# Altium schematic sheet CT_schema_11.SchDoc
size 742 x 377 mm
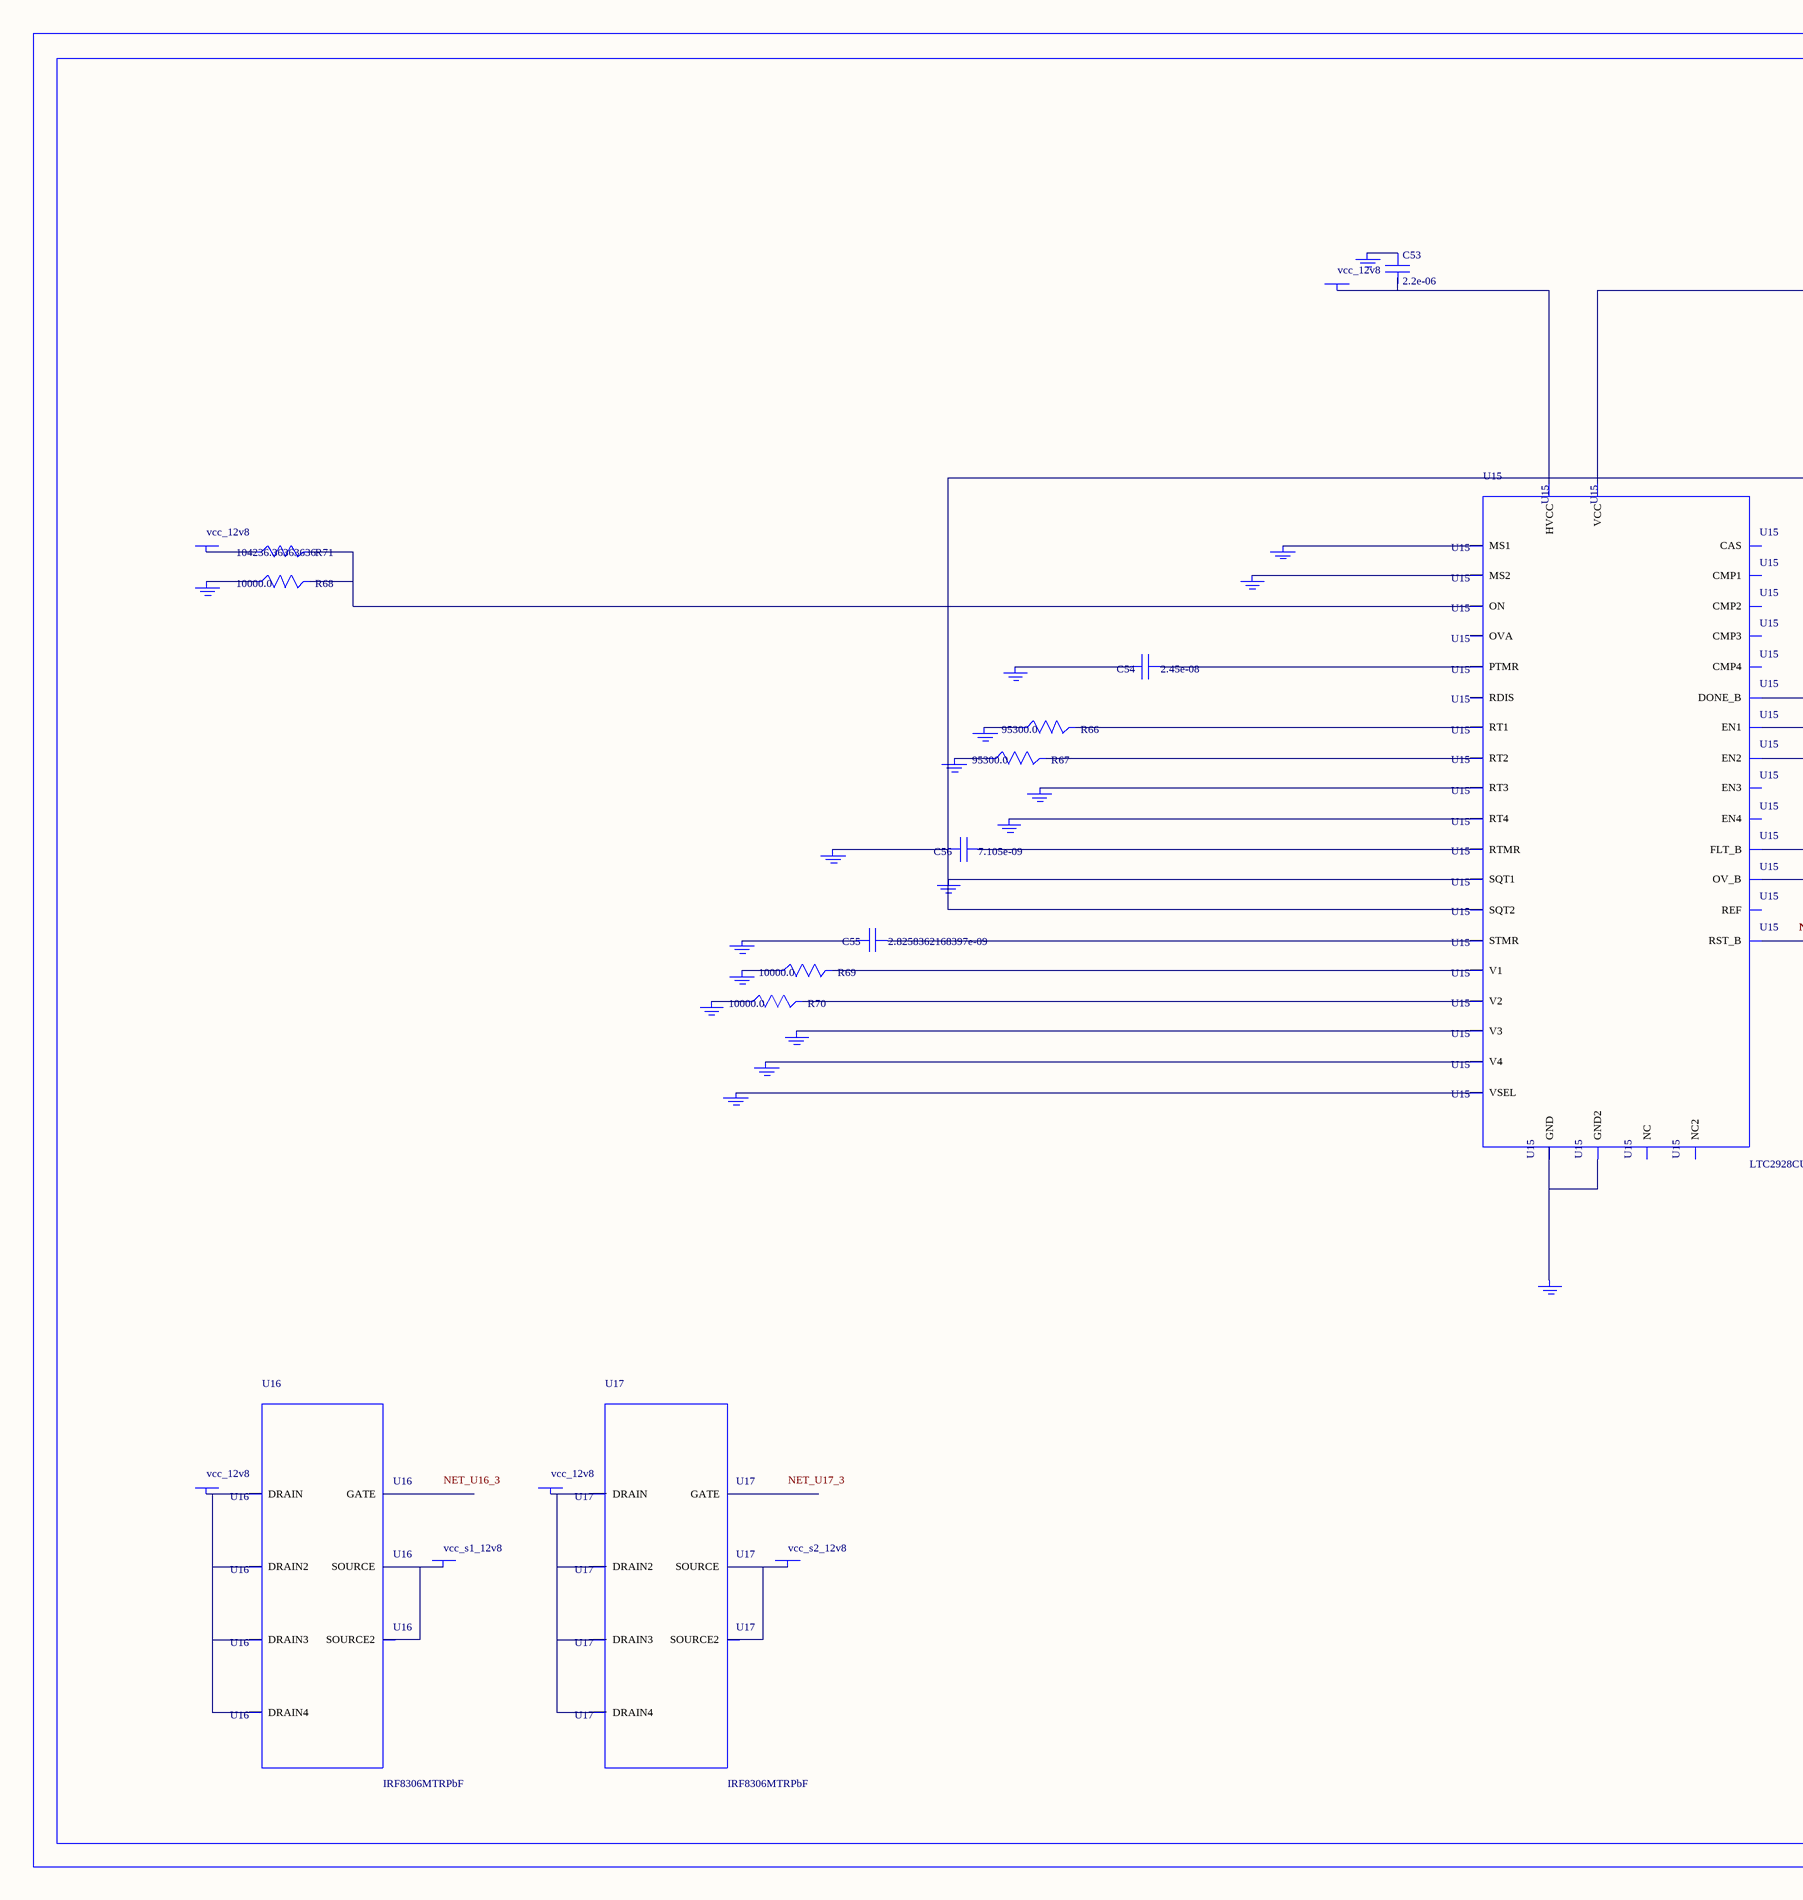
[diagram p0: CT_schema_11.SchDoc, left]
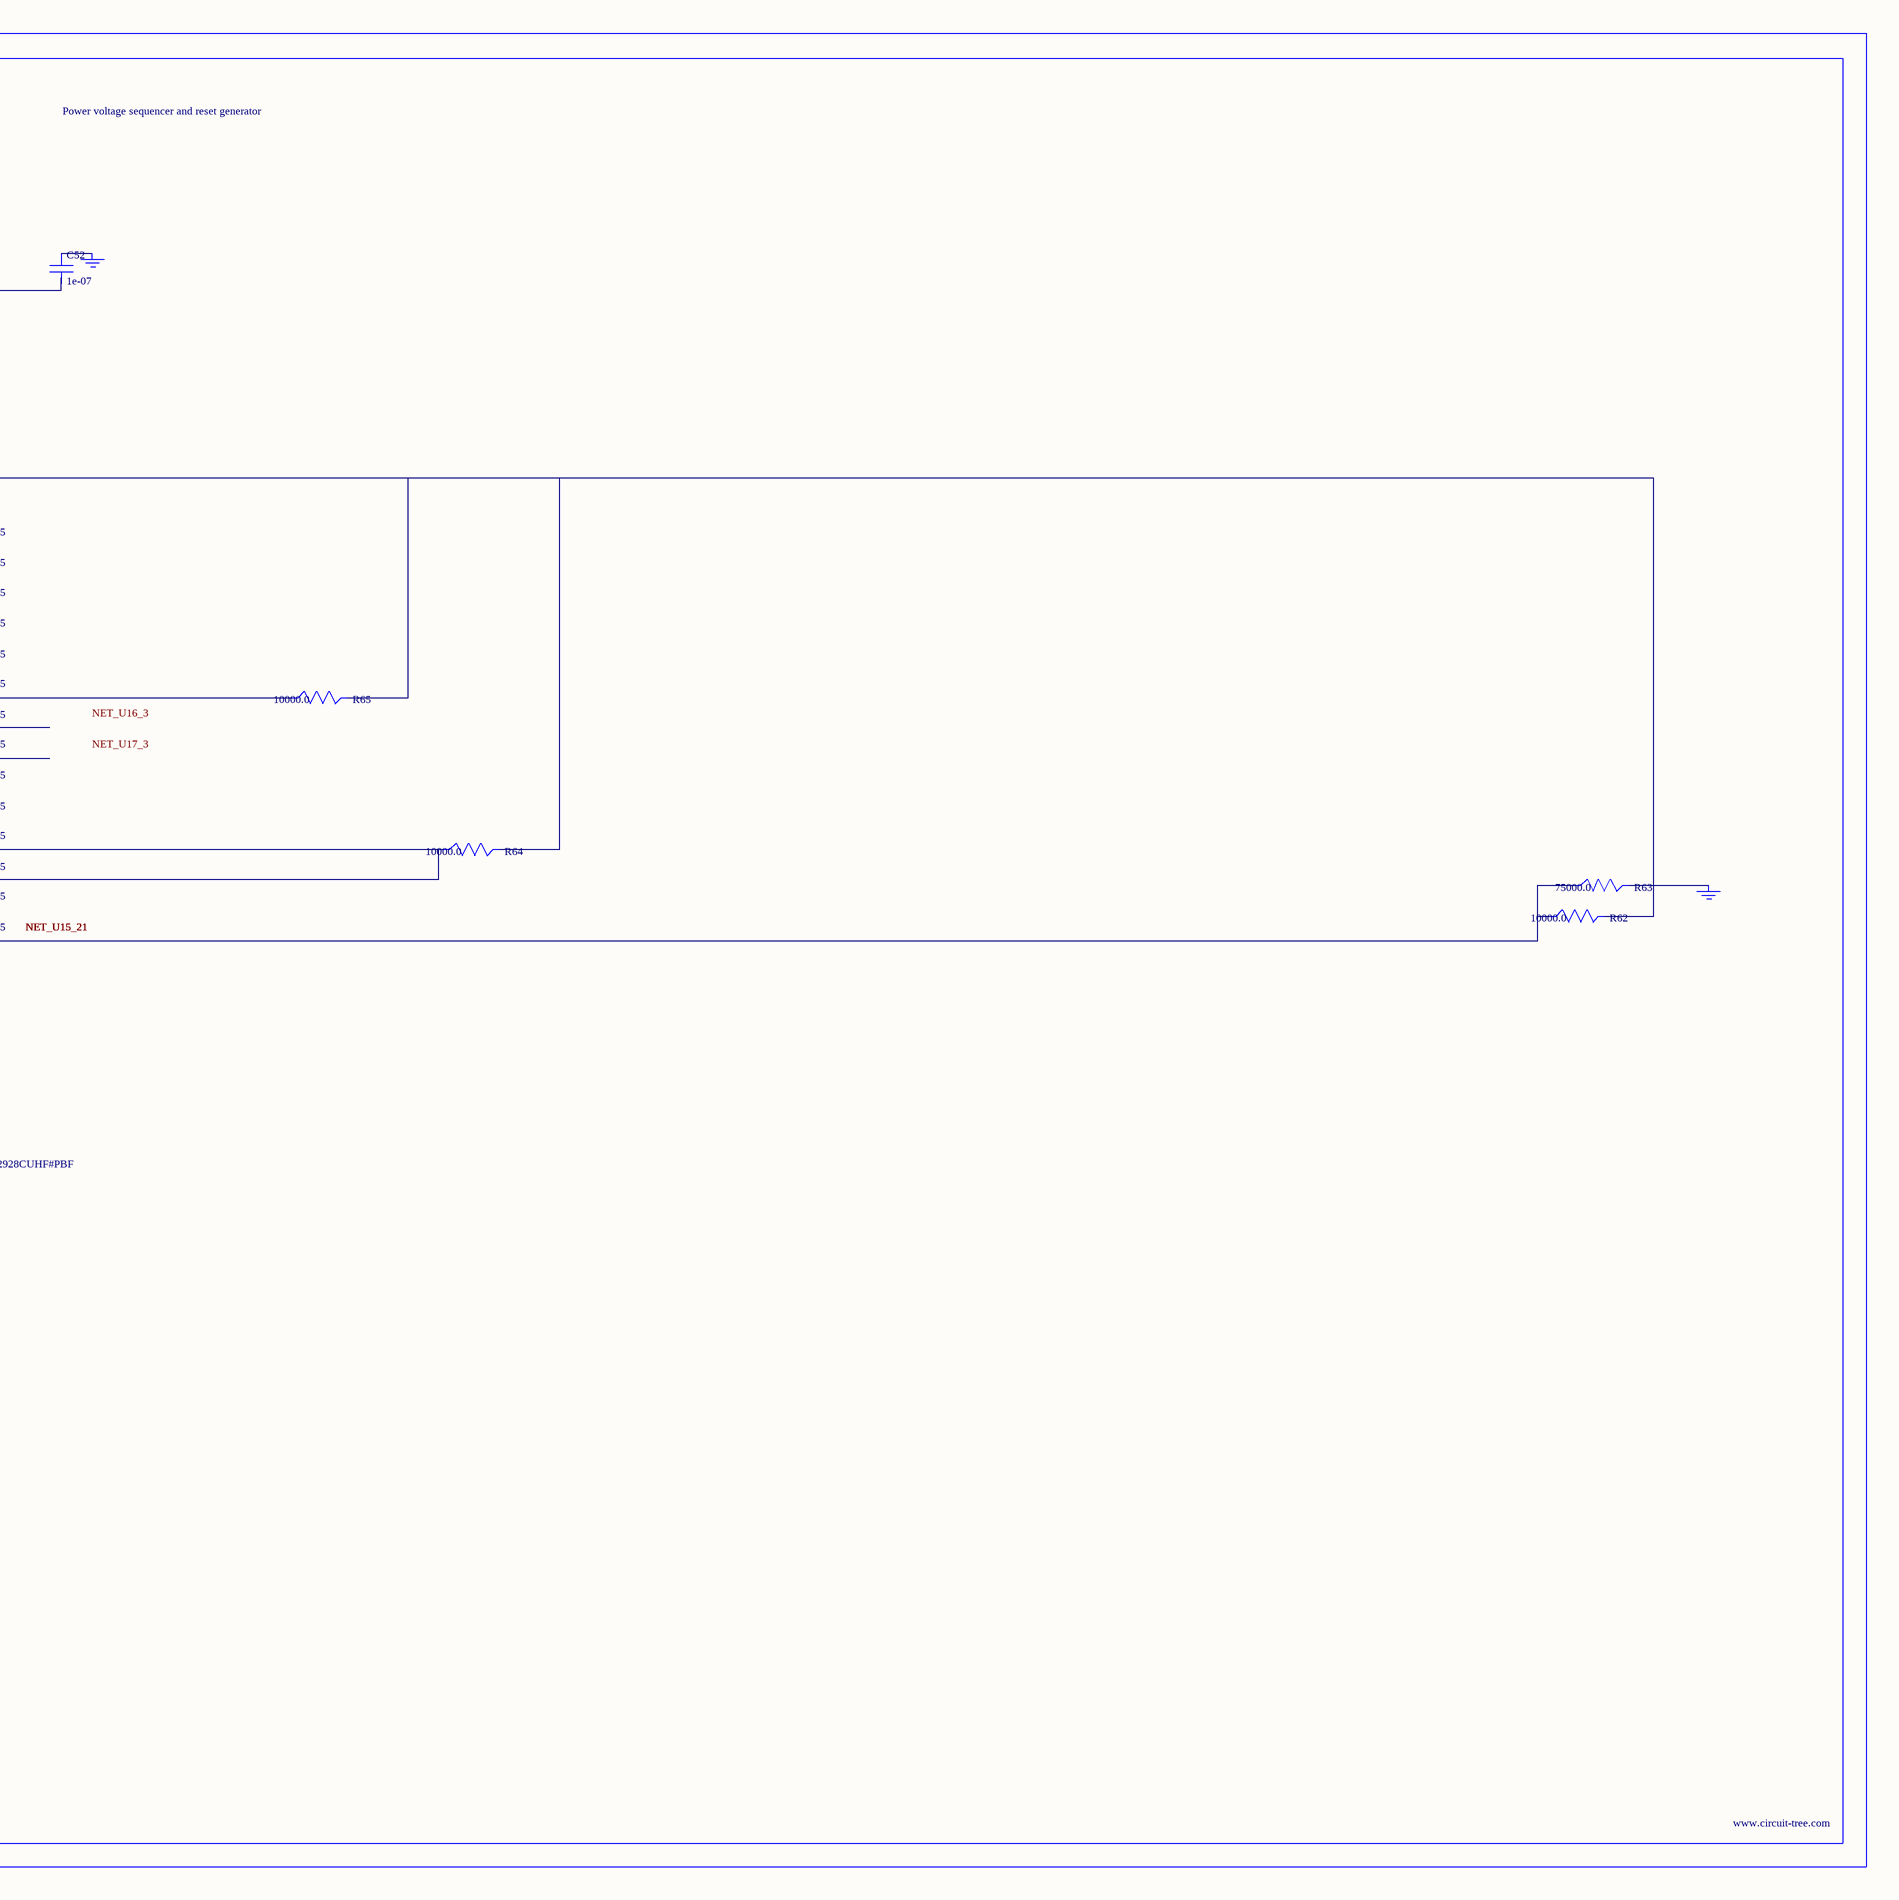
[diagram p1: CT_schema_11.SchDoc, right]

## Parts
BORDER10  (no value)
C52  1e-07  [C0402]
C53  2.2e-06  [C0603]
C54  2.45e-08  [R0603]
C55  2.8258362168397e-09  [R0603]
C56  7.105e-09  [R0603]
GND_INSTANCE_10_0  (no value)
GND_INSTANCE_10_1  (no value)
GND_INSTANCE_10_2  (no value)
GND_INSTANCE_10_3  (no value)
GND_INSTANCE_10_4  (no value)
GND_INSTANCE_10_5  (no value)
GND_INSTANCE_10_6  (no value)
GND_INSTANCE_10_7  (no value)
GND_INSTANCE_10_8  (no value)
GND_INSTANCE_10_9  (no value)
GND_INSTANCE_10_10  (no value)
GND_INSTANCE_10_11  (no value)
GND_INSTANCE_10_12  (no value)
GND_INSTANCE_10_13  (no value)
GND_INSTANCE_10_14  (no value)
GND_INSTANCE_10_15  (no value)
GND_INSTANCE_10_16  (no value)
GND_INSTANCE_10_17  (no value)
GND_INSTANCE_10_18  (no value)
GND_INSTANCE_10_19  (no value)
POWER_INSTANCE_10_0  vcc_12v8
POWER_INSTANCE_10_1  vcc_12v8
POWER_INSTANCE_10_2  vcc_12v8
POWER_INSTANCE_10_3  vcc_s1_12v8
POWER_INSTANCE_10_4  vcc_12v8
POWER_INSTANCE_10_5  vcc_s2_12v8
R62  10000.0  [R0603]
R63  75000.0  [R0603]
R64  10000.0  [R0603]
R65  10000.0  [R0603]
R66  95300.0  [R0603]
R67  95300.0  [R0603]
R68  10000.0  [R0603]
R69  10000.0  [R0603]
R70  10000.0  [R0603]
R71  104236.36363636  [R0603]
U15  LTC2928CUHF#PBF  [QFN-38_UHF]
U16  IRF8306MTRPbF  [IRF8306MTRPBF]
U17  IRF8306MTRPbF  [IRF8306MTRPBF]

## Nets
NetC52_1: C52.1 GND_INSTANCE_10_10.0(GND)
NetC52_2: C52.2 C56.2 GND_INSTANCE_10_5.0(GND) GND_INSTANCE_10_15.0(GND) R62.2 R64.2 R65.2 U15.10(SQT1) U15.11(SQT2) U15.22(VCC)
NetC53_1: C53.1 GND_INSTANCE_10_11.0(GND)
NetC53_2: C53.2 POWER_INSTANCE_10_1.0(PWR) U15.23(HVCC)
NetC54_1: C54.1 U15.27(PTMR)
NetC54_2: C54.2 GND_INSTANCE_10_14.0(GND)
NetC55_1: C55.1 U15.26(STMR)
NetC55_2: C55.2 GND_INSTANCE_10_13.0(GND)
NetC56_1: C56.1 U15.28(RTMR)
NetGND_INSTANCE_10_0_0: GND_INSTANCE_10_0.0(GND) R69.1
NetGND_INSTANCE_10_1_0: GND_INSTANCE_10_1.0(GND) R66.1
NetGND_INSTANCE_10_2_0: GND_INSTANCE_10_2.0(GND) R67.1
NetGND_INSTANCE_10_3_0: GND_INSTANCE_10_3.0(GND) U15.8(RT3)
NetGND_INSTANCE_10_4_0: GND_INSTANCE_10_4.0(GND) U15.9(RT4)
NetGND_INSTANCE_10_6_0: GND_INSTANCE_10_6.0(GND) U15.12(MS1)
NetGND_INSTANCE_10_7_0: GND_INSTANCE_10_7.0(GND) U15.13(MS2)
NetGND_INSTANCE_10_8_0: GND_INSTANCE_10_8.0(GND) R68.1
NetGND_INSTANCE_10_9_0: GND_INSTANCE_10_9.0(GND) R63.2
NetGND_INSTANCE_10_12_0: GND_INSTANCE_10_12.0(GND) U15.25(VSEL)
NetGND_INSTANCE_10_16_0: GND_INSTANCE_10_16.0(GND) U15.30(V4)
NetGND_INSTANCE_10_17_0: GND_INSTANCE_10_17.0(GND) U15.32(V3)
NetGND_INSTANCE_10_18_0: GND_INSTANCE_10_18.0(GND) R70.1
NetGND_INSTANCE_10_19_0: GND_INSTANCE_10_19.0(GND) U15.24(GND) U15.39(GND2)
NetPOWER_INSTANCE_10_0_0: POWER_INSTANCE_10_0.0(PWR) R71.1
NetPOWER_INSTANCE_10_2_0: POWER_INSTANCE_10_2.0(PWR) U16.1(DRAIN) U16.2(DRAIN2) U16.6(DRAIN3) U16.7(DRAIN4)
NetPOWER_INSTANCE_10_3_0: POWER_INSTANCE_10_3.0(PWR) U16.4(SOURCE) U16.5(SOURCE2)
NetPOWER_INSTANCE_10_4_0: POWER_INSTANCE_10_4.0(PWR) U17.1(DRAIN) U17.2(DRAIN2) U17.6(DRAIN3) U17.7(DRAIN4)
NetPOWER_INSTANCE_10_5_0: POWER_INSTANCE_10_5.0(PWR) U17.4(SOURCE) U17.5(SOURCE2)
NetR62_1: R62.1 R63.1 U15.21(RST_B)
NetR64_1: R64.1 U15.19(FLT_B) U15.20(OV_B)
NetR65_1: R65.1 U15.18(DONE_B)
NetR66_2: R66.2 U15.6(RT1)
NetR67_2: R67.2 U15.7(RT2)
NetR68_2: R68.2 R71.2 U15.16(ON)
NetR69_2: R69.2 U15.3(V1)
NetR70_2: R70.2 U15.38(V2)

Not connected (* = marked no-connect by the designer): U15 1(OVA) 2(EN1) 4(NC) 5(REF) 14(RDIS) 15(CAS) 17(NC2) 29(EN4) 31(EN3) 33(CMP3) 34(CMP4) 35(CMP1) 36(CMP2) 37(EN2); U16 3(GATE); U17 3(GATE)

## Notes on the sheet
- Labels drawn without touching a wire or pin: NET_U16_3, NET_U17_3

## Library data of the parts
BORDER10 = BORDER_PAGE10
C52 = C0402C104K3RACTU
C53 = GRM188R61H225KE1115D
C54 = C54
C55 = C55
C56 = C56
GND_INSTANCE_10_0-GND_INSTANCE_10_19 = GND
POWER_INSTANCE_10_0-POWER_INSTANCE_10_5 = PWR
R62 R64 R65 R68-R70 = RC0603JR-0710KL
R63 = RC0603JR-0775KL
R66 R67 = RC0603FR-0795K3L
R71 = R71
